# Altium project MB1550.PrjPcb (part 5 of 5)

## Sheet Camera.SchDoc: CAMERA
size A4; Date: Not used; ApprovedBy: Not used; CheckedBy: Not used; Author: Not used; CompanyName: STMicroelectronics; DrawnBy: Not used; Engineer: Not used; Organization: Not used; Address1: Not used; Address2: Not used; Address3: Not used; Address4: Not used; DocumentNumber: 17; Revision: Not used; SheetNumber: 17; SheetTotal: 24
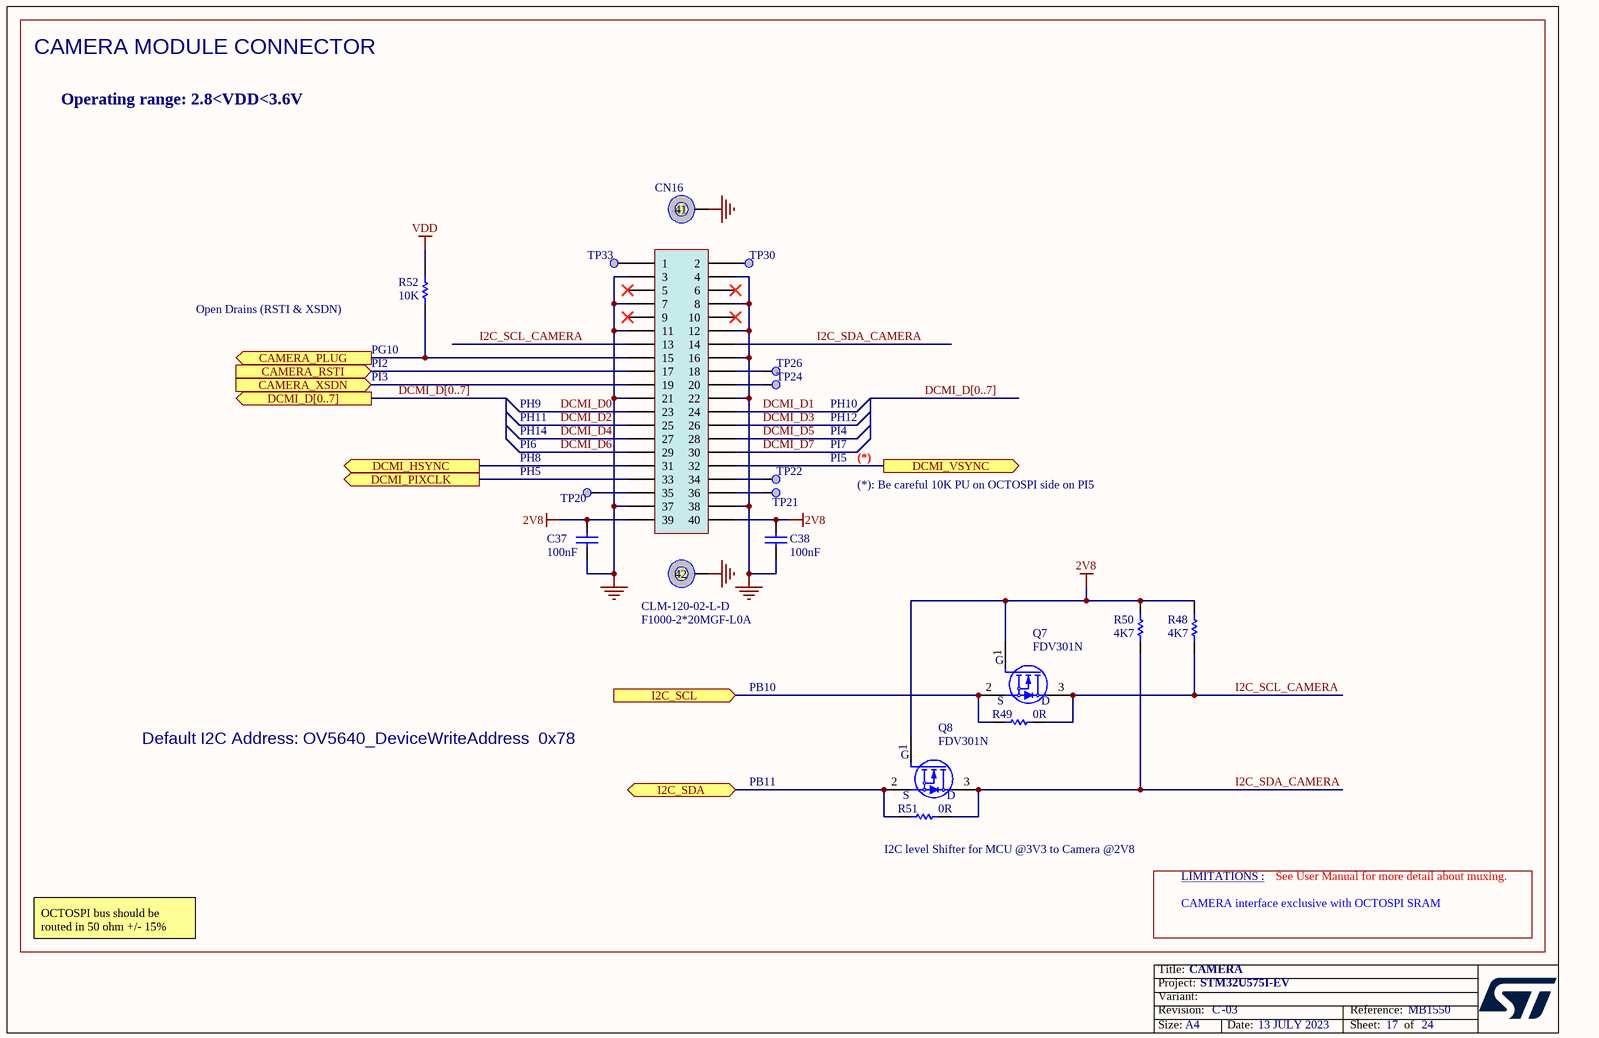
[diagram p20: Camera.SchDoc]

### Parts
C37  value 100nF  [C0402]
C38  value 100nF  [C0402]
CN16  value CLM-120-02-L-D  [CON_SAMTEC_CLM-120-02-L-D_Reverse-to-Camera]
Q7  value FDV301N  [MOS_SOT23]  (hidden comment: BSN20)
Q8  value FDV301N  [MOS_SOT23]  (hidden comment: BSN20)
R48  value 4K7  [R0402]
R49  value 0R  [R0603]  (hidden comment: Resistor)
R50  value 4K7  [R0402]
R51  value 0R  [R0603]  (hidden comment: Resistor)
R52  value 10K  [R0603]
TP20  Test Point  [TP_SMD_1MM]  (value not drawn)  (no BOM)
TP21  Test Point  [TP_SMD_1MM]  (value not drawn)  (no BOM)
TP22  Test Point  [TP_SMD_1MM]  (value not drawn)  (no BOM)
TP24  Test Point  [TP_SMD_1MM]  (value not drawn)  (no BOM)
TP26  Test Point  [TP_SMD_1MM]  (value not drawn)  (no BOM)
TP30  Test Point  [TP_SMD_1MM]  (value not drawn)  (no BOM)
TP33  Test Point  [TP_SMD_1MM]  (value not drawn)  (no BOM)

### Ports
CAMERA_PLUG (out), CAMERA_RSTI (in), CAMERA_XSDN (in), DCMI_D[0..7] (out), DCMI_HSYNC (out), DCMI_PIXCLK (out), DCMI_VSYNC (out), I2C_SCL (in), I2C_SDA (bidir)

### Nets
2V8: C37.2 C38.2 CN16.39 CN16.40 Q7.1(G) Q8.1(G) R48.2 R50.2
GND: C37.1 C38.1 CN16.3 CN16.4 CN16.7 CN16.8 CN16.11 CN16.12 CN16.16 CN16.21 CN16.22 CN16.37 CN16.38 CN16.41 CN16.42
VDD: R52.2
CAMERA_PLUG: CN16.15 R52.1 ; port CAMERA_PLUG
DCMI_D0: CN16.23
DCMI_D1: CN16.24
DCMI_D2: CN16.25
DCMI_D3: CN16.26
DCMI_D4: CN16.27
DCMI_D5: CN16.28
DCMI_D6: CN16.29
DCMI_D7: CN16.30
DCMI_PIXCLK: CN16.33 ; port DCMI_PIXCLK
I2C_SCL: Q7.2(S) R49.1 ; port I2C_SCL
I2C_SCL_CAMERA: CN16.13 Q7.3(D) R48.1 R49.2
I2C_SDA: Q8.2(S) R51.1 ; port I2C_SDA
I2C_SDA_CAMERA: CN16.14 Q8.3(D) R50.1 R51.2
PH8: CN16.31 ; port DCMI_HSYNC
PI2: CN16.17 ; port CAMERA_RSTI
PI3: CN16.19 ; port CAMERA_XSDN
PI5: CN16.32 ; port DCMI_VSYNC
NetCN16_1: CN16.1 TP33.1
NetCN16_2: CN16.2 TP30.1
NetCN16_18: CN16.18 TP26.1
NetCN16_20: CN16.20 TP24.1
NetCN16_34: CN16.34 TP22.1
NetCN16_35: CN16.35 TP20.1
NetCN16_36: CN16.36 TP21.1

Not connected (* = marked no-connect by the designer): CN16 5* 6* 9* 10*

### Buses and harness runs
bus DCMI_D[0..7]
bus DCMI_D[0..7] = port DCMI_D[0..7]

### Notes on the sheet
- CAMERA MODULE CONNECTOR
- Operating range: 2.8<VDD<3.6V
- Open Drains (RSTI & XSDN)
- (near R52) PG10
- PI2
- PI3
- PH9
- PH11
- PH14
- PI6
- PH10
- PH12
- PI4
- PI7
- PH8
- PH5
- PI5
- (*): Be careful 10K PU on OCTOSPI side on PI5
- (*)
- (near CN16) F1000-2*20MGF-L0A
- PB10
- Default I2C Address: OV5640_DeviceWriteAddress  0x78
- PB11
- (near R51) I2C level Shifter for MCU @3V3 to Camera @2V8
- LIMITATIONS :
- CAMERA interface exclusive with OCTOSPI SRAM
- See User Manual for more detail about muxing.
- OCTOSPI bus should be routed in 50 ohm +/- 15%

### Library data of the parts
C37 C38 = MCD-00006: Capacitor, MLCC, 100nF, 16V, X7R, 10%, 0402, T=0.5mm; Manufacturer_Part_Number: CC0402KRX7R7BB104; Manufacturer: YAGEO; Alternate_Manufacturer_Part_Number: GCM155R71C104KA55D; Alternate_Manufacturer: MURATA; Provided_By: SUBCO; ECCN_US: EAR99; ECCN_EU: NEC
CN16 = MCD-00138: Socket, 20x2, 1.0mm, VR, SMT, Height 2.26mm. Symbol & Footprint dedicated to MB1183 & MB1379 camera modules (not in line with Samtec datasheet); Part_Type: Connector; Provided_By: SUBCO; ECCN_US: EAR99; ECCN_EU: NEC
Q7 Q8 = MCD-02156: MOSFET, N-Channel , Vds: 25V, Id: 0,22A, Vgs(th): 1.06V, Vgs(max): +/-8V, Rdson:5ohm@Vgs=2.7V, Qg=0,49nC; Part_Type: Transistor; Manufacturer: ON SEMICONDUCTOR; ECCN_US: EAR99; ECCN_EU: NEC; Provided_By: SUBCO
R48 R50 = MCD-00065: Resistor,4K7,0402,1%,1/16W; Manufacturer_Part_Number: RC0402FR-074K7L; Manufacturer: YAGEO; Alternate_Manufacturer_Part_Number: RT0402FRE074K7L; Provided_By: SUBCO; ECCN_US: EAR99; ECCN_EU: NEC
R49 R51 = MCD-00056: Resistor,0R,0603,5%,1/10W; Manufacturer_Part_Number: RC0603JR-070RL; Manufacturer: YAGEO; Provided_By: SUBCO; ECCN_US: EAR99; ECCN_EU: NEC
R52 = MCD-00220: Resistor,10K,0603,1%,1/10W; Manufacturer_Part_Number: RC0603FR-0710KL; Manufacturer: YAGEO; Provided_By: Subcon; Initial_Board_Reference: MB1319
TP20-TP22 TP24 TP26 TP30 TP33 = MCD-00074: Test Point 1mm; Part_Type: Mechanical

## Sheet MFX_IO_expander.SchDoc: MFX IO EXPANDER
size A4; Date: Not used; ApprovedBy: Not used; CheckedBy: Not used; Author: Not used; CompanyName: STMicroelectronics; DrawnBy: Not used; Engineer: Not used; Organization: Not used; Address1: Not used; Address2: Not used; Address3: Not used; Address4: Not used; DocumentNumber: 6; Revision: Not used; SheetNumber: 6; SheetTotal: 24
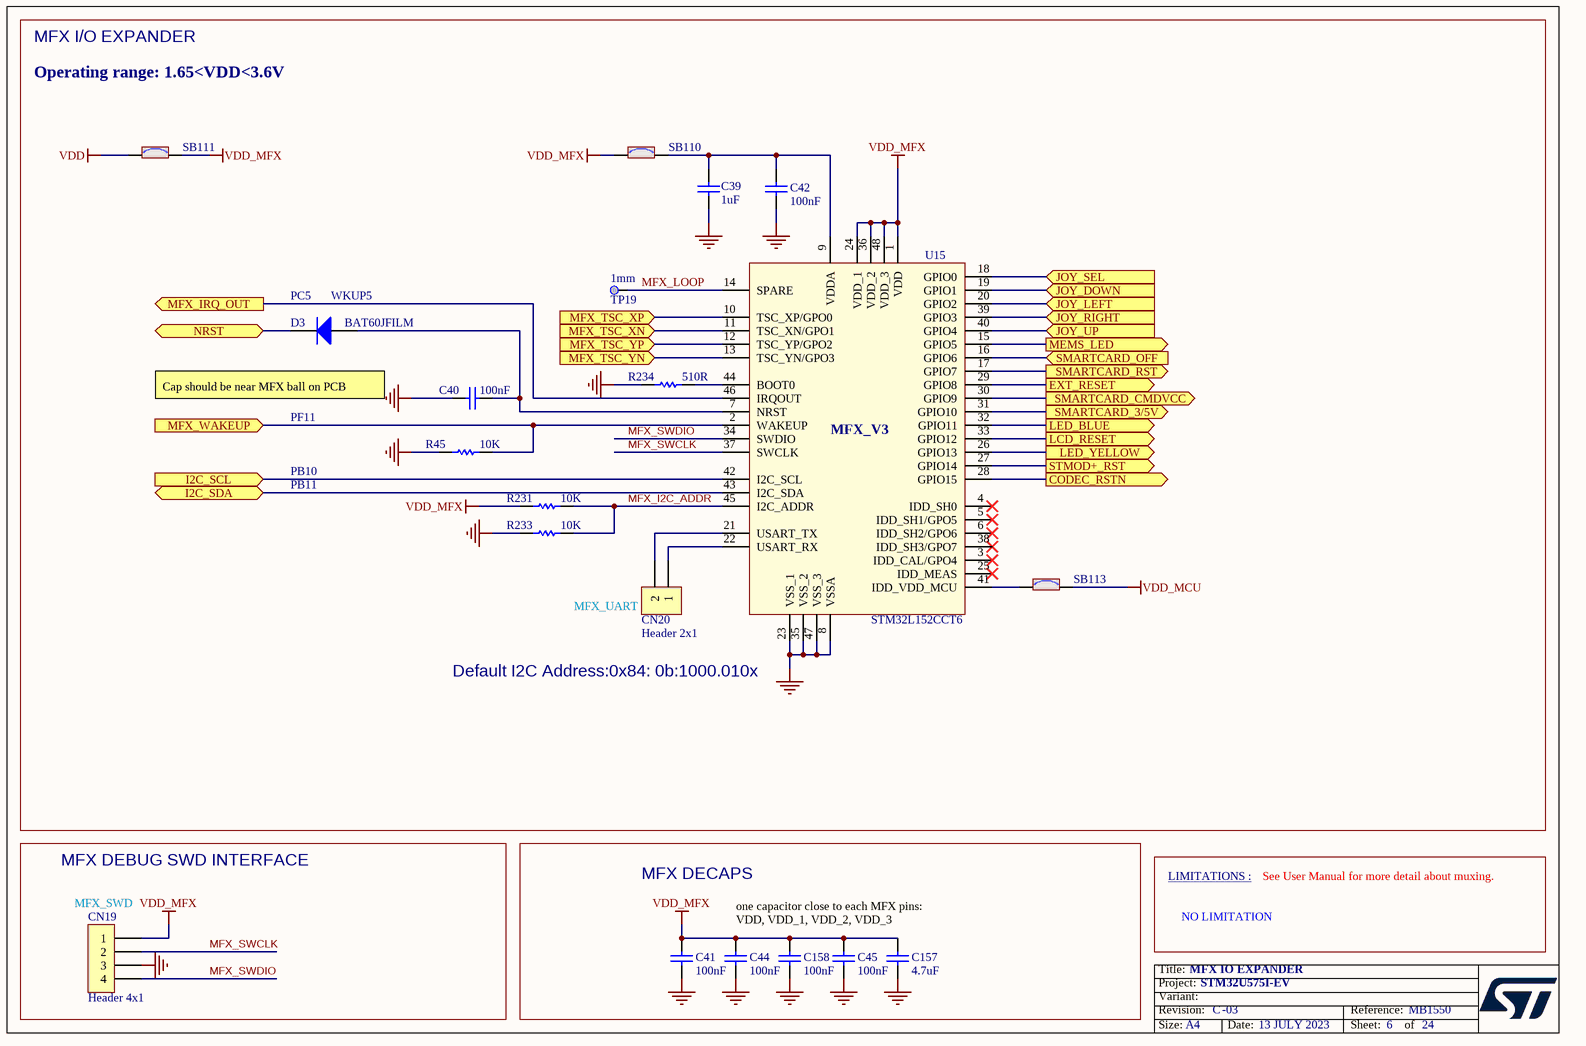
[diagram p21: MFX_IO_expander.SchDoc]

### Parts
C39  value 1uF  [C0603]
C40  value 100nF  [C0402]
C41  value 100nF  [C0402]
C42  value 100nF  [C0402]
C44  value 100nF  [C0402]
C45  value 100nF  [C0402]
C157  value 4.7uF  [C0603]
C158  value 100nF  [C0402]
CN19  value Header 4x1  [CON_SAMTEC_TSW-104-07-G-S]
CN20  value Header 2x1  [CON_SAMTEC_TSW-102-07-G-S]
D3  value BAT60JFILM  [DIO_SOD323]
R45  value 10K  [R0603]
R231  value 10K  [R0603]
R233  value 10K  [R0603]
R234  value 510R  [R0603]
SB110  (no value)  [SOLDER-BRIDGE_R0603-0R]
SB111  (no value)  [SOLDER-BRIDGE_R0603-0R]
SB113  (no value)  [SOLDER-BRIDGE_R0603-0R]
TP19  value 1mm  [TP_SMD_1MM]  (no BOM)
U15  value STM32L152CCT6  [ICC_LQFP48_7X7_P050]

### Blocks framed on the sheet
MFX DEBUG SWD INTERFACE: CN19
MFX DECAPS: C41 C44 C45 C157 C158

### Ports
CODEC_RSTN (out), EXT_RESET (out), I2C_SCL (in), I2C_SDA (bidir), JOY_DOWN (in), JOY_LEFT (in), JOY_RIGHT (in), JOY_SEL (in), JOY_UP (in), LCD_RESET (out), LED_BLUE (out), LED_YELLOW (out), MEMS_LED (out), MFX_IRQ_OUT (out), MFX_TSC_XN (in), MFX_TSC_XP (in), MFX_TSC_YN (in), MFX_TSC_YP (in), MFX_WAKEUP (in), NRST (bidir), SMARTCARD_3/5V (out), SMARTCARD_CMDVCC (out), SMARTCARD_OFF (in), SMARTCARD_RST (out), STMOD+_RST (out)

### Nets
GND: C39.1 C40.2 C41.1 C42.1 C44.1 C45.1 C157.1 C158.2 CN19.3 R45.1 R233.1 R234.1 U15.8(VSSA) U15.23(VSS_1) U15.35(VSS_2) U15.47(VSS_3)
VDD: SB111.1
VDD_MCU: SB113.2
VDD_MFX: C41.2 C44.2 C45.2 C157.2 C158.1 CN19.1 R231.1 SB110.1 SB111.2 U15.1(VDD) U15.24(VDD_1) U15.36(VDD_2) U15.48(VDD_3)
CODEC_RSTN: U15.28(GPIO15) ; port CODEC_RSTN
EXT_RESET: U15.29(GPIO8) ; port EXT_RESET
I2C_SCL: U15.42(I2C_SCL) ; port I2C_SCL
I2C_SDA: U15.43(I2C_SDA) ; port I2C_SDA
JOY_DOWN: U15.19(GPIO1) ; port JOY_DOWN
JOY_LEFT: U15.20(GPIO2) ; port JOY_LEFT
JOY_RIGHT: U15.39(GPIO3) ; port JOY_RIGHT
JOY_SEL: U15.18(GPIO0) ; port JOY_SEL
JOY_UP: U15.40(GPIO4) ; port JOY_UP
LCD_RESET: U15.33(GPIO12) ; port LCD_RESET
LED_BLUE: U15.32(GPIO11) ; port LED_BLUE
LED_YELLOW: U15.26(GPIO13) ; port LED_YELLOW
MEMS_LED: U15.15(GPIO5) ; port MEMS_LED
MFX_I2C_ADDR: R231.2 R233.2 U15.45(I2C_ADDR)
MFX_IRQ_OUT: U15.46(IRQOUT) ; port MFX_IRQ_OUT
MFX_LOOP: TP19.1 U15.14(SPARE)
MFX_SWCLK: CN19.2 U15.37(SWCLK)
MFX_SWDIO: CN19.4 U15.34(SWDIO)
MFX_TSC_XN: U15.11(TSC_XN/GPO1) ; port MFX_TSC_XN
MFX_TSC_XP: U15.10(TSC_XP/GPO0) ; port MFX_TSC_XP
MFX_TSC_YN: U15.13(TSC_YN/GPO3) ; port MFX_TSC_YN
MFX_TSC_YP: U15.12(TSC_YP/GPO2) ; port MFX_TSC_YP
MFX_WAKEUP: R45.2 U15.2(WAKEUP) ; port MFX_WAKEUP
NRST: D3.2(K) ; port NRST
SmartCard_3/5V: U15.31(GPIO10) ; port SMARTCARD_3/5V
SMARTCARD_CMDVCC: U15.30(GPIO9) ; port SMARTCARD_CMDVCC
SMARTCARD_OFF: U15.16(GPIO6) ; port SMARTCARD_OFF
SMARTCARD_RST: U15.17(GPIO7) ; port SMARTCARD_RST
STMOD+_RST: U15.27(GPIO14) ; port STMOD+_RST
NetC39_2: C39.2 C42.2 SB110.2 U15.9(VDDA)
NetC40_1: C40.1 D3.1(A) U15.7(NRST)
NetCN20_1: CN20.1 U15.22(USART_RX)
NetCN20_2: CN20.2 U15.21(USART_TX)
NetR234_2: R234.2 U15.44(BOOT0)
NetSB113_1: SB113.1 U15.41(IDD_VDD_MCU)

Not connected (* = marked no-connect by the designer): U15 3(IDD_CAL/GPO4)* 4(IDD_SH0)* 5(IDD_SH1/GPO5)* 6(IDD_SH2/GPO6)* 25(IDD_MEAS)* 38(IDD_SH3/GPO7)*

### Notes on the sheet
- MFX I/O EXPANDER
- Operating range: 1.65<VDD<3.6V
- (near D3) PC5
- (near D3) WKUP5
- (near D3) Cap should be near MFX ball on PCB
- PF11
- PB10
- PB11
- (near CN20) MFX_UART
- Default I2C Address:0x84: 0b:1000.010x
- (near CN19) MFX_SWD
- LIMITATIONS :
- NO LIMITATION
- See User Manual for more detail about muxing.
- one capacitor close to each MFX pins: VDD, VDD_1, VDD_2, VDD_3

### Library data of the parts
C39 = MCD-00010: Capacitor, MLCC, 1uF, 16V, X5R, 10%, 0603, T=0,8mm; Manufacturer_Part_Number: CC0603KRX5R7BB105; Manufacturer: YAGEO; Provided_By: Subcon; Initial_Board_Reference: MB1274
C40-C42 C44 C45 C158 = MCD-00006: as C37 on sheet Camera
C157 = MCD-00009: Capacitor, MLCC, 4.7uF, 16V, X5R, 10%, 0603, T=0.8mm; Manufacturer_Part_Number: CC0603KRX5R7BB475; Manufacturer: YAGEO; ECCN_US: EAR99; ECCN_EU: NEC; Provided_By: SUBCO
CN19 = MCD-00029: Header, 4x1, 2,54mm, VR, TH, Height 5.84mm/2.54mm; Manufacturer_Part_Number: TSW-104-07-x-S; Manufacturer: SAMTEC; Part_Type: Connector; Provided_By: Subcon; Initial_Board_Reference: MB1274
CN20 = MCD-00032: Header, 2x1, 2,54mm, VR, TH, Height 5.84mm/2.54mm; Part_Type: Connector; Manufacturer_Part_Number: TSW-102-07-x-S; Manufacturer: SAMTEC; Provided_By: Subcon; Initial_Board_Reference: MB1274
D3 = MCD-00034: BAT60JFILM; Manufacturer: STMICROELECTRONICS; Part_Type: Diode; ECCN_US: EAR99; ECCN_EU: NEC; Provided_By: Subcon; Initial_Board_Reference: MB1274
R45 R231 R233 = MCD-00220: as R52 on sheet Camera
R234 = MCD-00225: Resistor,510R,0603,1%,1/10W; Manufacturer_Part_Number: RC0603FR-07510RL; Manufacturer: YAGEO; Provided_By: Subcon; Initial_Board_Reference: MB1319
SB110 SB111 SB113 = MCD-00071: Solder Bridge ON; Part_Type: Mechanical; Provided_By: Subcon; Initial_Board_Reference: MB1274
TP19 = MCD-00074: Test Point 1mm; Part_Type: Mechanical; Initial_Board_Reference: MB1274
U15 = MCD-00135: Ultra-low-power 32-bit MCU ARM; Part_Type: IC; Manufacturer: STMICROELECTRONICS; BMS_Part_Number: 9175875; ECCN_US: 3A991A2; ECCN_EU: NEC; Provided_By: SUBCO with ST control

## Sheet STPMS2.SchDoc: STPMS2
size A4; Date: Not used; ApprovedBy: Not used; CheckedBy: Not used; Author: Not used; CompanyName: STMicroelectronics; DrawnBy: Not used; Engineer: Not used; Organization: Not used; Address1: Not used; Address2: Not used; Address3: Not used; Address4: Not used; DocumentNumber: 18; Revision: Not used; SheetNumber: 18; SheetTotal: 24
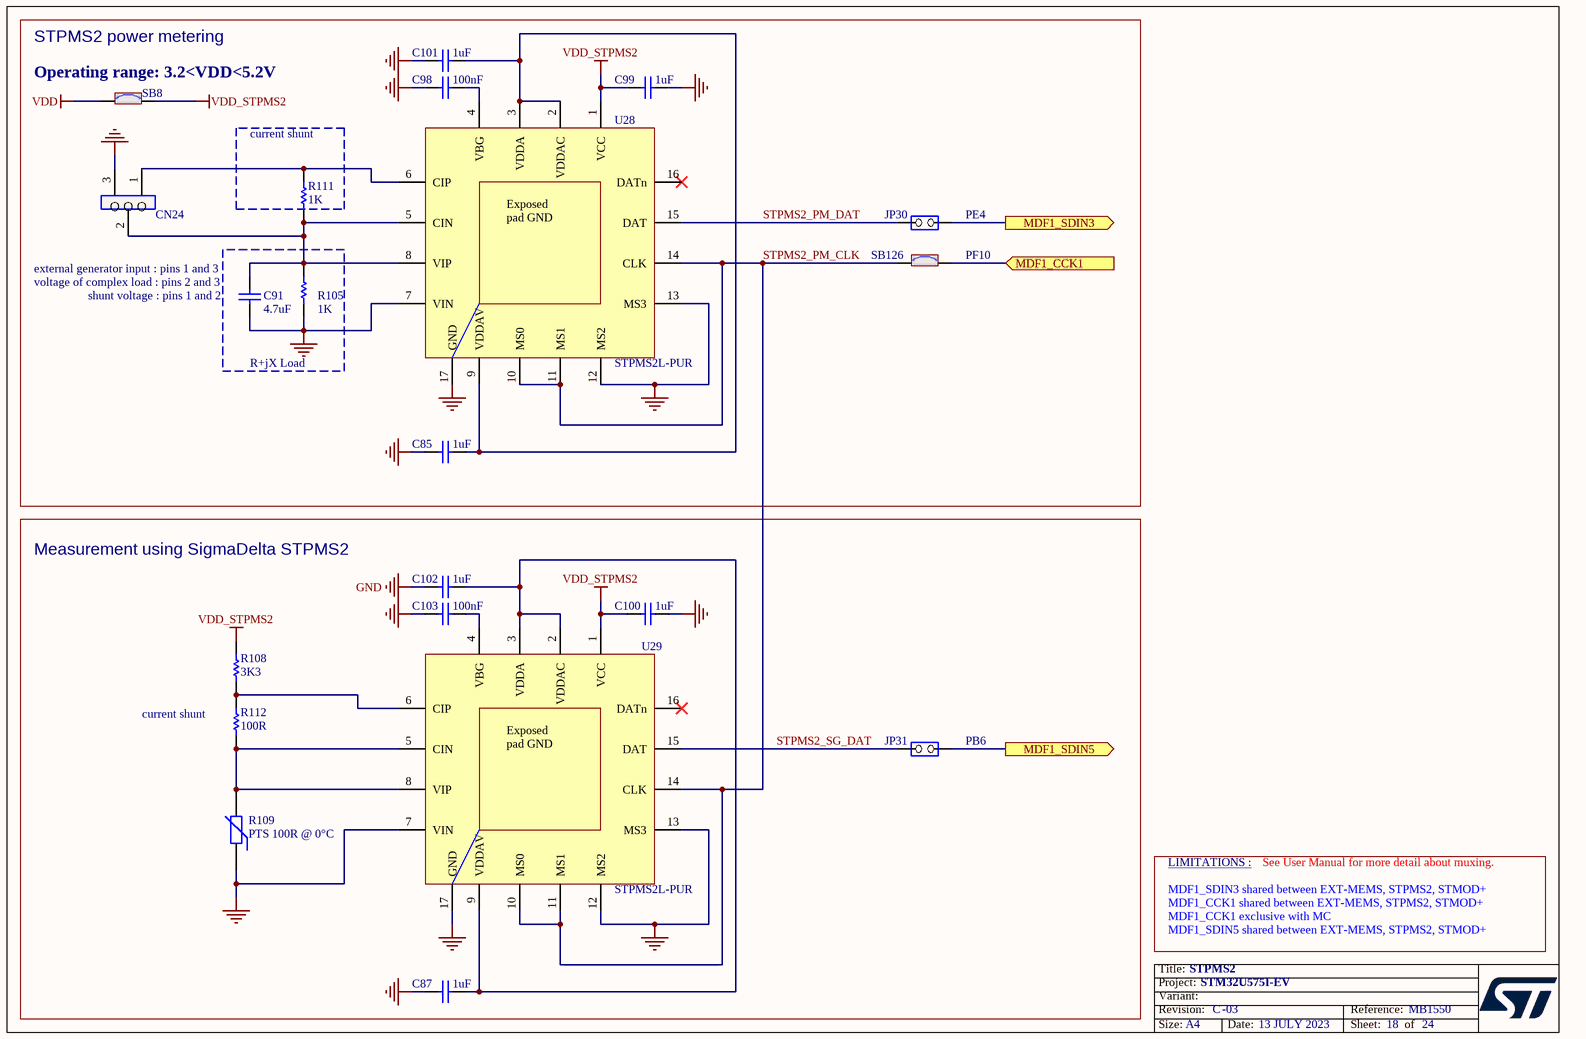
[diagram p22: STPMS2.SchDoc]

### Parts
C85  value 1uF  [C0603]
C87  value 1uF  [C0603]
C91  value 4.7uF  [C0603]
C98  value 100nF  [C0402]
C99  value 1uF  [C0603]
C100  value 1uF  [C0603]
C101  value 1uF  [C0603]
C102  value 1uF  [C0603]
C103  value 100nF  [C0402]
CN24  (no value)  [CON_SAMTEC_TSW-103-07-F-S]
JP30  Jumper_Header 2x1  [CON_SAMTEC_TSW-102-07-G-S]  (value not drawn)
JP31  Jumper_Header 2x1  [CON_SAMTEC_TSW-102-07-G-S]  (value not drawn)
R105  value 1K  [R0603]
R108  value 3K3  [R0603]
R109  value PTS 100R @ 0°C  [R0603_H0P45]  (hidden comment: PT100)
R111  value 1K  [R0603]
R112  value 100R  [R0603]
SB8  (no value)  [SOLDER-BRIDGE_R0603-0R]
SB126  (no value)  [SOLDER-BRIDGE_R0603-0R]
U28  value STPMS2L-PUR  [ICC_QFN16-EPAD_4X4_P065]
U29  value STPMS2L-PUR  [ICC_QFN16-EPAD_4X4_P065]

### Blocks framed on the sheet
STPMS2 power metering: C85 C98 C99 C101 CN24 JP30 SB8 SB126 U28
current shunt: R111
R+jX Load: C91 R105
Measurement using SigmaDelta STPMS2: C87 C100 C102 C103 JP31 R108 R109 R112 U29

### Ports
MDF1_CCK1 (in), MDF1_SDIN3 (out), MDF1_SDIN5 (out)

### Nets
GND: C85.1 C87.2 C91.1 C98.2 C99.1 C100.1 C101.2 C102.2 C103.1 CN24.3 R105.1 R109.1 U28.7(VIN) U28.12(MS2) U28.13(MS3) U28.17(GND) U29.7(VIN) U29.12(MS2) U29.13(MS3) U29.17(GND)
VDD: SB8.1
VDD_STPMS2: C99.2 C100.2 R108.2 SB8.2 U28.1(VCC) U29.1(VCC)
MDF1_CCK1: SB126.2 ; port MDF1_CCK1
MDF1_SDIN3: JP30.2(NO) ; port MDF1_SDIN3
MDF1_SDIN5: JP31.2(NO) ; port MDF1_SDIN5
STPMS2_PM_CLK: SB126.1 U28.10(MS0) U28.11(MS1) U28.14(CLK) U29.10(MS0) U29.11(MS1) U29.14(CLK)
STPMS2_PM_DAT: JP30.1(COMMON) U28.15(DAT)
STPMS2_SG_DAT: JP31.1(COMMON) U29.15(DAT)
NetC85_2: C85.2 C101.1 U28.2(VDDAC) U28.3(VDDA) U28.9(VDDAV)
NetC87_1: C87.1 C102.1 U29.2(VDDAC) U29.3(VDDA) U29.9(VDDAV)
NetC91_2: C91.2 CN24.2 R105.2 R111.1 U28.5(CIN) U28.8(VIP)
NetC98_1: C98.1 U28.4(VBG)
NetC103_2: C103.2 U29.4(VBG)
NetCN24_1: CN24.1 R111.2 U28.6(CIP)
NetR108_1: R108.1 R112.2 U29.6(CIP)
NetR109_2: R109.2 R112.1 U29.5(CIN) U29.8(VIP)

Not connected (* = marked no-connect by the designer): U28 16(DATn)*; U29 16(DATn)*

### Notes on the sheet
- (near SB8) Operating range: 3.2<VDD<5.2V
- PE4
- (near C91) external generator input : pins 1 and 3
- (near C91) voltage of complex load : pins 2 and 3
- (near C91) shunt voltage : pins 1 and 2
- (near SB126) PF10
- (near R112) current shunt
- (near JP31) PB6
- LIMITATIONS :
- MDF1_CCK1 shared between EXT-MEMS, STPMS2, STMOD+
- MDF1_CCK1 exclusive with MC
- MDF1_SDIN3 shared between EXT-MEMS, STPMS2, STMOD+
- See User Manual for more detail about muxing.
- MDF1_SDIN5 shared between EXT-MEMS, STPMS2, STMOD+

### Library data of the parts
C85 C87 C99-C102 = MCD-00010: as C39 on sheet MFX_IO_expander
C91 = MCD-00009: as C157 on sheet MFX_IO_expander
C98 C103 = MCD-00006: as C37 on sheet Camera
CN24 = MCD-00111: Header, 3x1, 2,54mm, VR, TH, Height 5.84mm/2.54mm; Manufacturer_Part_Number: TSW-103-07-F-S; Manufacturer: SAMTEC; Part_Type: Connector; Value: Header 3x1; Provided_By: Subcon; ECCN_US: EAR99; ECCN_EU: NEC; Initial_Board_Reference: MB1262
JP30 JP31 = MCD-00045: Header, 2x1, 2,54mm, VR, TH, Height 5.84mm/2.54mm; Part_Type: Connector; Manufacturer_Part_Number: TSW-102-07-x-S; Manufacturer: SAMTEC; Value: Shunt not fitted; Provided_By: Subcon; Initial_Board_Reference: MB1274; Remark: 3D KO: BZ: 40098
R105 R111 = MCD-00070: Resistor,1K,0603,1%,1/10W; Manufacturer_Part_Number: RC0603FR-071KL; Manufacturer: YAGEO; Provided_By: Subcon; Initial_Board_Reference: MB1274
R108 = MCD-00352: Resistor,3K3,0603,1%,1/10W; Manufacturer_Part_Number: RC0603FR-073K3L; Manufacturer: YAGEO; Provided_By: Subcon
R109 = MCD-00680: Resistor, SMD PTS 100ohm @ 0°C Flat Chip Temperature Sensor; Manufacturer_Part_Number: PTS060301B100RP100; Manufacturer: VISHAY; Provided_By: Subcon; Initial_Board_Reference: MB1331
R112 = MCD-00224: Resistor,100R,0603,1%,1/10W; Manufacturer_Part_Number: RC0603FR-07100RL; Manufacturer: YAGEO; Provided_By: Subcon; Initial_Board_Reference: MB1319
SB8 SB126 = MCD-00071: as SB110 on sheet MFX_IO_expander
U28 U29 = MCD-00681: Smart sensor II dual-channel 1-bit, 4 MHz, second-order sigmadelta modulator with embedded PGLNA; Part_Type: IC; Manufacturer: STMICROELECTRONICS; ECCN_US: EAR99; ECCN_EU: NEC; Provided_By: STM; Initial_Board_Reference: MB1331

## Sheet SENSOR_and_I2C-interface.SchDoc: SENSOR & I2C PERIPHERALS
size A4; Date: Not used; ApprovedBy: Not used; CheckedBy: Not used; Author: Not used; CompanyName: STMicroelectronics; DrawnBy: Not used; Engineer: Not used; Organization: Not used; Address1: Not used; Address2: Not used; Address3: Not used; Address4: Not used; DocumentNumber: 16; Revision: Not used; SheetNumber: 16; SheetTotal: 24
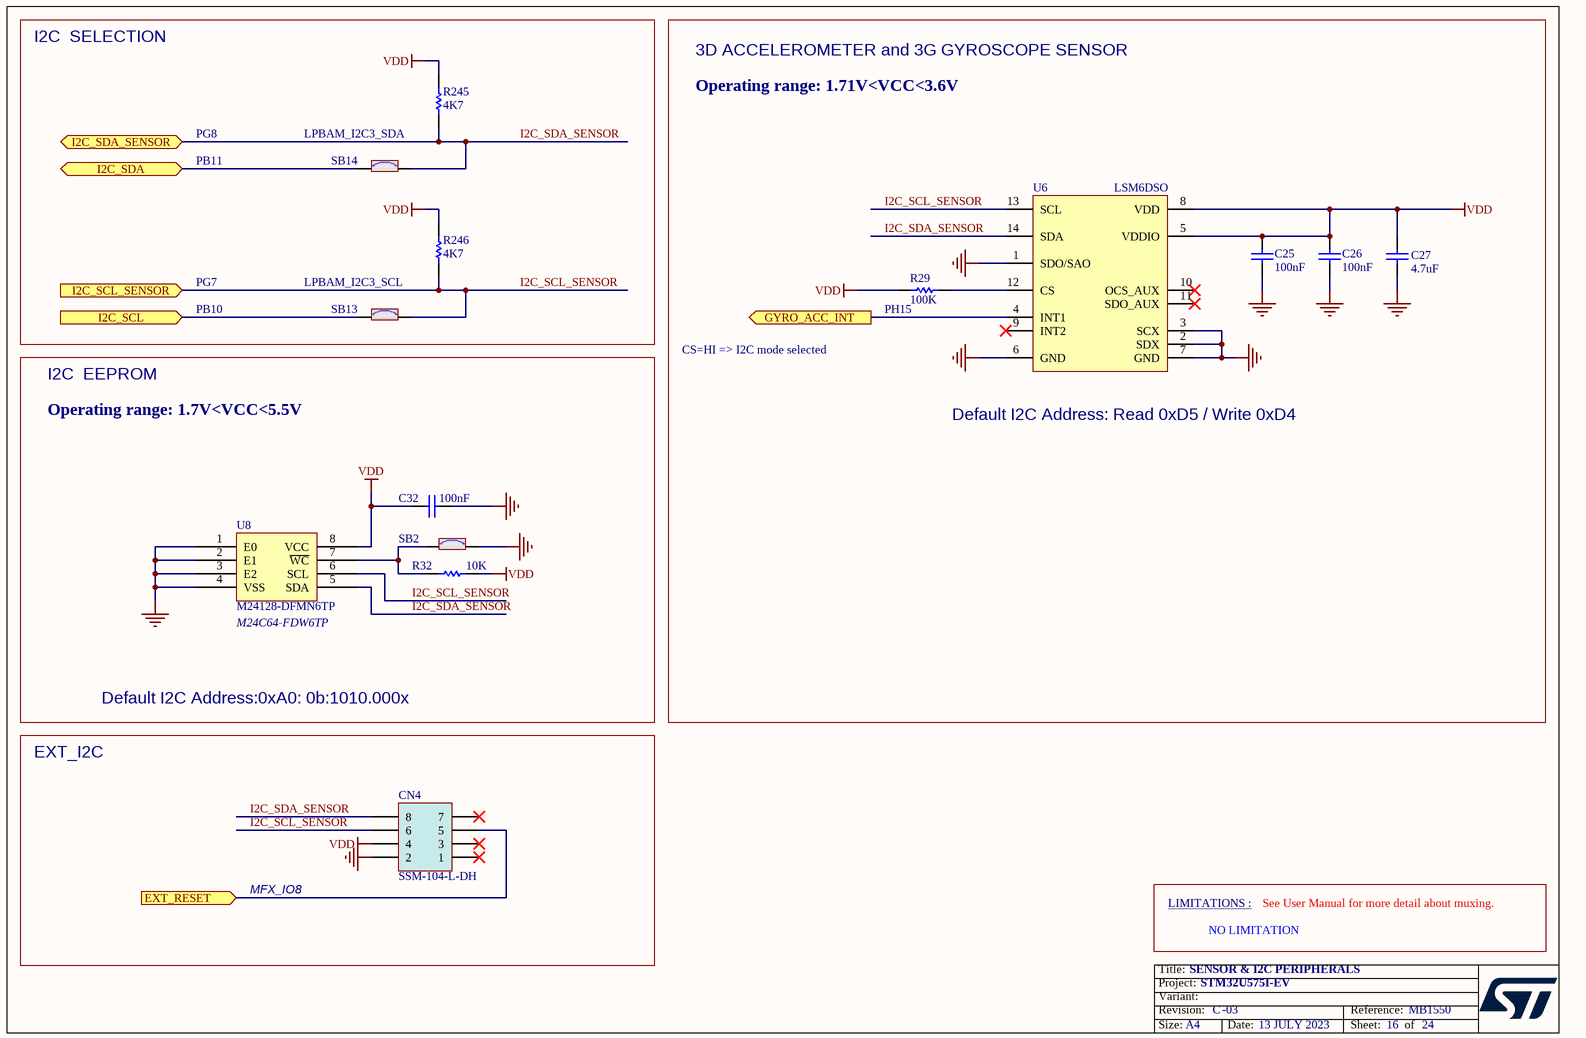
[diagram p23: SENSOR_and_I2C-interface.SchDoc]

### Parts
C25  value 100nF  [C0402]
C26  value 100nF  [C0402]
C27  value 4.7uF  [C0603]
C32  value 100nF  [C0402]
CN4  value SSM-104-L-DH  [CON_SAMTEC_SSM-104-L-DH]
R29  value 100K  [R0603]
R32  value 10K  [R0603]
R245  value 4K7  [R0603]  (hidden comment: Resistor)
R246  value 4K7  [R0603]  (hidden comment: Resistor)
SB2  (no value)  [SOLDER-BRIDGE_R0603-0R]
SB13  (no value)  [SOLDER-BRIDGE_R0603-0R]
SB14  (no value)  [SOLDER-BRIDGE_R0603-0R]
U6  LSM6DSO  [ICC_LGA14_3X2P5_P050]
U8  value M24128-DFMN6TP  [ICC_SO8_5X4_P127]

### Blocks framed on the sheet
I2C  SELECTION: R245 R246 SB13 SB14
EXT_I2C: CN4

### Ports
EXT_RESET (in), GYRO_ACC_INT (out), I2C_SCL (in), I2C_SCL_SENSOR (in), I2C_SDA (bidir), I2C_SDA_SENSOR (bidir)

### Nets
GND: C25.1 C26.1 C27.1 C32.1 CN4.2 SB2.2 U6.1(SDO/SAO) U6.2(SDX) U6.3(SCX) U6.6(GND) U6.7(GND) U8.1(E0) U8.2(E1) U8.3(E2) U8.4(VSS)
VDD: C25.2 C26.2 C27.2 C32.2 CN4.4 R29.2 R32.1 R245.2 R246.2 U6.5(VDDIO) U6.8(VDD) U8.8(VCC)
EXT_RESET: CN4.5 ; port EXT_RESET
GYRO_ACC_INT: U6.4(INT1) ; port GYRO_ACC_INT
I2C_SCL: SB13.1 ; port I2C_SCL
I2C_SCL_SENSOR: CN4.6 R246.1 SB13.2 U6.13(SCL) U8.6(SCL) ; port I2C_SCL_SENSOR
I2C_SDA: SB14.1 ; port I2C_SDA
I2C_SDA_SENSOR: CN4.8 R245.1 SB14.2 U6.14(SDA) U8.5(SDA) ; port I2C_SDA_SENSOR
NetR29_1: R29.1 U6.12(CS)
NetR32_2: R32.2 SB2.1 U8.7(~{WC})

Not connected (* = marked no-connect by the designer): CN4 1* 3* 7*; U6 9(INT2)* 10(OCS_AUX)* 11(SDO_AUX)*

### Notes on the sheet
- 3D ACCELEROMETER and 3G GYROSCOPE SENSOR
- Operating range: 1.71V<VCC<3.6V
- PB11
- PG8
- (near SB14) LPBAM_I2C3_SDA
- PB10
- PG7
- (near SB13) LPBAM_I2C3_SCL
- (near R29) PH15
- I2C  EEPROM
- CS=HI => I2C mode selected
- Operating range: 1.7V<VCC<5.5V
- (near U6) Default I2C Address: Read 0xD5 / Write 0xD4
- (near U8) M24C64-FDW6TP
- Default I2C Address:0xA0: 0b:1010.000x
- MFX_IO8
- LIMITATIONS :
- See User Manual for more detail about muxing.
- NO LIMITATION

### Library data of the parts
C25 C26 C32 = MCD-00006: as C37 on sheet Camera
C27 = MCD-00009: as C157 on sheet MFX_IO_expander
CN4 = MCD-00131: Socket, 4x2, 2.54mm, RA, SMT, Height 5.72mm; Manufacturer: SAMTEC; Part_Type: Connector; Provided_By: Subcon; ECCN_US: EAR99; ECCN_EU: NEC; Initial_Board_Reference: MB1262
R29 = MCD-00223: Resistor,100K,0603,1%,1/10W; Manufacturer_Part_Number: RC0603FR-07100KL; Manufacturer: YAGEO; Provided_By: Subcon; Initial_Board_Reference: MB1319
R32 = MCD-00220: as R52 on sheet Camera
R245 R246 = MCD-00219: Resistor,4K7,0603,1%,1/10W; Manufacturer_Part_Number: RC0603FR-074K7L; Manufacturer: YAGEO; Part_Preference: Recommended
SB2 SB13 SB14 = MCD-00071: as SB110 on sheet MFX_IO_expander
U6 = MCD-01499: iNEMO inertial module: always-on 3D accelerometer and 3D gyroscope; Part_Type: IC; Manufacturer: STMICROELECTRONICS; BMS_Part_Number: 9177993; ECCN_US: EAR99; ECCN_EU: NEC; Provided_By: SUBCO with ST control
U8 = MCD-00293: I2C memory; Part_Type: IC; Manufacturer: STMICROELECTRONICS; Provided_By: Subcon; Initial_Board_Reference: MB1329

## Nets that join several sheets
1V8: AUDIO (SB121.1), BOARD_PWR (SB7.2 TP34.1)
2V8: BOARD_PWR (SB104.2 TP16.1), Camera (8 pins)
3V3: BOARD_PWR (6 pins), Extension_Connector (CN9.50 CN14.34 CN15.34), FDCAN_RS232 (R78.1 SB56.1), MCU_PWR (JP5.1 JP17.3 JP23.1), MOTOR_CONTROL (CN2.28 R5.2 R6.1), PERIPHERAL (R130.2 R131.2 R132.2 R133.2), PMOD_STMOD+ (C1.2 R3.2 U1.2), USB_TYPEC (R1.2 R4.1 SB10.1 U42.2), LCD_TFT_320x240 (SB125.1 SB128.1), ST_LINK_V3E (R100.2)
5V: BOARD_PWR (14 pins), Extension_Connector (CN10.50), FDCAN_RS232 (SB5.1), MOTOR_CONTROL (CN2.25), PMOD_STMOD+ (CN7.6 CN7.15), SMARTCARD (SB118.1), LCD_TFT_320x240 (SB127.1), ST_LINK_V3E (R106.1)
5V_DC: BOARD_PWR (JP25.7), Extension_Connector (CN9.49), ST_LINK_V3E (D5.1)
5V_EXT: BOARD_PWR (7 pins), ST_LINK_V3E (D7.1)
5V_STLK: BOARD_PWR (JP25.1), ST_LINK_V3E (C61.1 U20.1)
5V_UCPD: BOARD_PWR (JP25.5), USB_TYPEC (JP6.1 JP7.1 JP8.1), ST_LINK_V3E (D6.1)
5V_USB_CHGR: BOARD_PWR (JP25.9), ST_LINK_V3E (8 pins)
GND: Top (H3.1 H4.1 H5.1 H6.1), AUDIO (34 pins), BOARD_PWR (42 pins), Extension_Connector (21 pins), FDCAN_RS232 (22 pins), JTAG_TRACE (26 pins), MCU_CLOCK_&_RESET (17 pins), MCU_IO (JP9.2 JP13.2), MCU_PWR (38 pins), MOTOR_CONTROL (26 pins), OCTOSPI (14 pins), PERIPHERAL (19 pins), PMOD_STMOD+ (8 pins), SDCARD (12 pins), SMARTCARD (17 pins), SRAM (6 pins), USB_TYPEC (29 pins), LCD_TFT_320x240 (13 pins), ST_LINK_V3E (107 pins), Camera (15 pins), MFX_IO_expander (16 pins), STPMS2 (20 pins), SENSOR_and_I2C-interface (15 pins)
VDD: AUDIO (9 pins), Extension_Connector (CN9.47 CN14.33 CN15.33), FDCAN_RS232 (6 pins), JTAG_TRACE (8 pins), MCU_CLOCK_&_RESET (5 pins), MCU_IO (R147.2 R149.2), MCU_PWR (JP19.1 JP23.2 JP24.1 TP12.1), OCTOSPI (SB28.1 SB109.1), PERIPHERAL (R34.1 R43.1 RV1.3), PMOD_STMOD+ (CN3.6 CN3.12), SDCARD (SB93.1), SMARTCARD (SB122.1), SRAM (SB106.1), LCD_TFT_320x240 (SB123.1), ST_LINK_V3E (7 pins), Camera (R52.2), MFX_IO_expander (SB111.1), STPMS2 (SB8.1), SENSOR_and_I2C-interface (12 pins)
VDD_ADJ: BOARD_PWR (SB3.2 TP29.1), MCU_PWR (JP23.3)
VDD_MCU: MCU_PWR (26 pins), MFX_IO_expander (SB113.2)
A0: MCU_IO (R205.2), SRAM (U12.A3)
A1: MCU_IO (R208.2), SRAM (U12.A4)
A2: MCU_IO (R214.2), SRAM (U12.A5)
A3: MCU_IO (R218.2), SRAM (U12.B3)
A4: MCU_IO (R223.2), SRAM (U12.B4)
A5: MCU_IO (R227.2), SRAM (U12.C3)
A6: MCU_IO (R225.2), SRAM (U12.C4)
A7: MCU_IO (R221.2), SRAM (U12.D4)
A8: MCU_IO (R219.2), SRAM (U12.H2)
A9: MCU_IO (R215.2), SRAM (U12.H3)
A10: MCU_IO (R209.2), SRAM (U12.H4)
A11: MCU_IO (R203.2), SRAM (U12.H5)
A12: MCU_IO (R217.2), SRAM (U12.G3)
A13: MCU_IO (R222.2), SRAM (U12.G4)
A14: MCU_IO (R226.2), SRAM (U12.F3)
A15: MCU_IO (R229.2), SRAM (U12.F4)
A16: MCU_IO (R196.1), SRAM (U12.E4)
A17: MCU_IO (R199.1), SRAM (U12.D3)
A18: MCU_IO (R204.1), SRAM (U12.H1)
A19: MCU_IO (R189.1), SRAM (U12.G2)
A20: MCU_IO (R191.2), SRAM (R38.1 U12.H6)
ADC_DAC: MCU_IO (SB16.2), PERIPHERAL (R144.2)
ADF1_CCK0: AUDIO (TP36.1 U37.16), MCU_IO (SB115.2)
ADF1_SDIN0: AUDIO (TP35.1 U37.5), MCU_IO (SB26.2)
BOOTLOADER_BOOT0: FDCAN_RS232 (U43.20), MCU_CLOCK_&_RESET (D1.1)
BOOTLOADER_RST: FDCAN_RS232 (R161.2 U43.16), MCU_CLOCK_&_RESET (D9.2)
CAMERA_PLUG: MCU_IO (SB103.2), Camera (CN16.15 R52.1)
CODEC_RSTN: AUDIO (R85.2 U25.25), MFX_IO_expander (U15.28)
COMP2_INP: MCU_IO (SB40.2), PERIPHERAL (JP22.1)
COMP2_OUT: MCU_IO (SB39.2), PERIPHERAL (TP9.1)
D0: MCU_IO (R207.1), SRAM (U12.B6), LCD_TFT_320x240 (CN23.6)
D1: MCU_IO (R213.1), SRAM (U12.C5), LCD_TFT_320x240 (CN23.7)
D2: MCU_IO (R228.1), SRAM (U12.C6), LCD_TFT_320x240 (CN23.8)
D3: MCU_IO (R224.1), SRAM (U12.D5), LCD_TFT_320x240 (CN23.9)
D4: MCU_IO (R200.1), SRAM (U12.E5), LCD_TFT_320x240 (CN23.10)
D5: MCU_IO (R197.1), SRAM (U12.F5), LCD_TFT_320x240 (CN23.11)
D6: MCU_IO (R193.1), SRAM (U12.F6), LCD_TFT_320x240 (CN23.12)
D7: MCU_IO (R188.1), SRAM (U12.G6), LCD_TFT_320x240 (CN23.13)
D8: MCU_IO (R185.1), SRAM (U12.B1), LCD_TFT_320x240 (CN23.14)
D9: MCU_IO (R182.1), SRAM (U12.C1), LCD_TFT_320x240 (CN23.15)
D10: MCU_IO (R180.1), SRAM (U12.C2), LCD_TFT_320x240 (CN23.16)
D11: MCU_IO (R175.1), SRAM (U12.D2), LCD_TFT_320x240 (CN23.17)
D12: MCU_IO (R183.1), SRAM (U12.E2), LCD_TFT_320x240 (CN23.18)
D13: MCU_IO (R186.1), SRAM (U12.F2), LCD_TFT_320x240 (CN23.19)
D14: MCU_IO (R190.1), SRAM (U12.F1), LCD_TFT_320x240 (CN23.20)
D15: MCU_IO (R192.1), SRAM (U12.G1), LCD_TFT_320x240 (CN23.21)
DCMI_D0: Extension_Connector (CN10.17), MCU_IO (SB95.1 U5.E9), Camera (CN16.23)
DCMI_D1: Extension_Connector (CN10.18), MCU_IO (SB97.1 U5.C13), Camera (CN16.24)
DCMI_D2: Extension_Connector (CN10.20), MCU_IO (SB99.1 U5.D9), Camera (CN16.25)
DCMI_D3: Extension_Connector (CN10.21), MCU_IO (SB100.1 U5.B13), Camera (CN16.26)
DCMI_D4: Extension_Connector (CN10.22), MCU_IO (U5.C11), Camera (CN16.27)
DCMI_D5: Extension_Connector (CN10.8), MCU_IO (U5.B10), Camera (CN16.28)
DCMI_D6: Extension_Connector (CN10.12), MCU_IO (U5.A2), Camera (CN16.29)
DCMI_D7: Extension_Connector (CN10.11), MCU_IO (U5.C3), Camera (CN16.30)
DCMI_PIXCLK: MCU_IO (R145.1), Camera (CN16.33)
EXT_RESET: MFX_IO_expander (U15.29), SENSOR_and_I2C-interface (CN4.5)
FMC_A22_LCD_RS: MCU_IO (R198.1), LCD_TFT_320x240 (CN23.2)
FMC_NBL0: MCU_IO (R176.1), SRAM (U12.A1)
FMC_NBL1: MCU_IO (R181.1), SRAM (U12.B2)
FMC_NE1: MCU_IO (R202.1), SRAM (R37.1 U12.B5)
FMC_NE4_LCD_CSn: MCU_IO (R187.2), LCD_TFT_320x240 (CN23.1)
FMC_NOE: MCU_IO (R216.1), SRAM (U12.A2), LCD_TFT_320x240 (CN23.4)
FMC_NWE: MCU_IO (R210.1), SRAM (U12.G5), LCD_TFT_320x240 (CN23.3)
GYRO_ACC_INT: MCU_IO (SB27.1), SENSOR_and_I2C-interface (U6.4)
I2C_SCL: AUDIO (U25.3), MCU_IO (R147.1 SB46.1 TP8.1), PMOD_STMOD+ (CN7.7), USB_TYPEC (U42.18), LCD_TFT_320x240 (SB138.2 U35.9), Camera (Q7.2 R49.1), MFX_IO_expander (U15.42), SENSOR_and_I2C-interface (SB13.1)
I2C_SCL_SENSOR: MCU_IO (JP10.1), SENSOR_and_I2C-interface (5 pins)
I2C_SDA: AUDIO (U25.2), MCU_IO (R149.1 SB49.1 TP7.1), PMOD_STMOD+ (CN7.10), USB_TYPEC (U42.17), LCD_TFT_320x240 (SB141.2 U35.8), Camera (Q8.2 R51.1), MFX_IO_expander (U15.43), SENSOR_and_I2C-interface (SB14.1)
I2C_SDA_SENSOR: MCU_IO (JP11.1), SENSOR_and_I2C-interface (5 pins)
IBUS_SENSE: MCU_IO (SB72.2), USB_TYPEC (U42.4)
JOY_DOWN: PERIPHERAL (B1.3 U38.4), MFX_IO_expander (U15.19)
JOY_LEFT: PERIPHERAL (B1.1 U38.6), MFX_IO_expander (U15.20)
JOY_RIGHT: PERIPHERAL (B1.6 U38.3), MFX_IO_expander (U15.39)
JOY_SEL: PERIPHERAL (B1.2 U38.5), MFX_IO_expander (U15.18)
JOY_UP: PERIPHERAL (B1.4 U38.1), MFX_IO_expander (U15.40)
JTCK_SWCLK: Extension_Connector (CN10.4), JTAG_TRACE (R58.2), MCU_IO (U5.C10), ST_LINK_V3E (CN13.4 CN18.6 R71.1 U17.4)
JTDI: JTAG_TRACE (R46.2), MCU_IO (SB15.2), ST_LINK_V3E (CN13.8 CN18.10 U17.1)
JTDO_SWO: JTAG_TRACE (R62.2), MCU_IO (SB114.2), ST_LINK_V3E (CN13.6 CN18.8 R70.1 U17.3)
JTMS_SWDIO: Extension_Connector (CN10.2), JTAG_TRACE (R54.2), MCU_IO (U5.F12), ST_LINK_V3E (CN13.2 CN18.4 R72.1 U17.5)
JTRSTN: JTAG_TRACE (R40.2), MCU_IO (SB32.2), ST_LINK_V3E (CN13.9)
LCD_CTP_INT: MCU_IO (SB35.2), LCD_TFT_320x240 (R119.1 SB137.2 U35.7)
LCD_RESET: LCD_TFT_320x240 (CN23.5), MFX_IO_expander (U15.33)
LCD_TE: MCU_IO (SB117.2), LCD_TFT_320x240 (SB143.2)
LED_BLUE: PERIPHERAL (R238.1), MFX_IO_expander (U15.32)
LED_YELLOW: PERIPHERAL (R237.1), MFX_IO_expander (U15.26)
MC_BUS_VOLTAGE: MCU_IO (SB17.2), MOTOR_CONTROL (C15.2 CN2.14 R7.2)
MC_CURRENT_A: MCU_IO (SB63.2), MOTOR_CONTROL (C11.1 CN2.15)
MC_CURRENT_B: MCU_IO (SB66.2), MOTOR_CONTROL (C4.1 CN2.17)
MC_CURRENT_C: MCU_IO (SB73.2), MOTOR_CONTROL (C3.2 CN2.19)
MC_DISSIPATIVE_BRAKE: MCU_IO (SB45.2), MOTOR_CONTROL (CN2.23)
MC_EMERGENCY_STOP: MCU_IO (SB43.2), MOTOR_CONTROL (C10.1 CN2.1 R6.2)
MC_ENCODER_A: MCU_IO (SB65.2), MOTOR_CONTROL (C8.1 CN2.31 SB1.1)
MC_ENCODER_B: MCU_IO (SB67.2), MOTOR_CONTROL (C6.1 CN2.33)
MC_ENCODER_INDEX: MCU_IO (SB48.2), MOTOR_CONTROL (C7.2 CN2.34)
MC_ICL_SHUTOUT: MCU_IO (SB107.2), MOTOR_CONTROL (CN2.21)
MC_PFC_IND_CURR: MCU_IO (SB69.2), MOTOR_CONTROL (C14.2 CN2.24)
MC_PFC_PWM: MCU_IO (SB58.2), MOTOR_CONTROL (C9.1 CN2.29)
MC_PFC_SHUTDOWN: MCU_IO (SB44.2), MOTOR_CONTROL (C2.2 CN2.30 R5.1)
MC_PFC_SYNC: MCU_IO (SB59.2), MOTOR_CONTROL (C12.2 CN2.27)
MC_PFC_VAC: MCU_IO (SB57.2), MOTOR_CONTROL (C5.2 CN2.32)
MC_PWM_1H: MCU_IO (SB29.2), MOTOR_CONTROL (CN2.3)
MC_PWM_1L: MCU_IO (SB61.2), MOTOR_CONTROL (CN2.5)
MC_PWM_2H: MCU_IO (SB30.2), MOTOR_CONTROL (CN2.7)
MC_PWM_2L: MCU_IO (SB50.2), MOTOR_CONTROL (CN2.9)
MC_PWM_3H: MCU_IO (SB80.2), MOTOR_CONTROL (CN2.11)
MC_PWM_3L: MCU_IO (SB54.2), MOTOR_CONTROL (CN2.13)
MC_TEMP: MCU_IO (SB51.2), MOTOR_CONTROL (C13.2 CN2.26)
MDF1_CCK0: AUDIO (TP37.1 U37.8), MCU_IO (SB119.2)
MDF1_CCK1: AUDIO (CN29.3), MCU_IO (SB55.2), PMOD_STMOD+ (CN7.18 R146.1), STPMS2 (SB126.2)
MDF1_SDIN0: AUDIO (TP38.1 U37.13), MCU_IO (R220.1)
MDF1_SDIN3: AUDIO (CN29.5), MCU_IO (SB105.2), PMOD_STMOD+ (CN7.17), STPMS2 (JP30.2)
MDF1_SDIN5: AUDIO (CN29.7), MCU_IO (SB41.2), PMOD_STMOD+ (CN7.19), STPMS2 (JP31.2)
MEMS_LED: AUDIO (CN29.12), MFX_IO_expander (U15.15)
MFX_IRQ_OUT: MCU_IO (SB70.2), MFX_IO_expander (U15.46)
MFX_TSC_XN: LCD_TFT_320x240 (SB142.2), MFX_IO_expander (U15.11)
MFX_TSC_XP: LCD_TFT_320x240 (SB136.2), MFX_IO_expander (U15.10)
MFX_TSC_YN: LCD_TFT_320x240 (SB140.2), MFX_IO_expander (U15.13)
MFX_TSC_YP: LCD_TFT_320x240 (SB139.2), MFX_IO_expander (U15.12)
MFX_WAKEUP: MCU_IO (SB60.2), MFX_IO_expander (R45.2 U15.2)
NRST: Extension_Connector (R156.1), JTAG_TRACE (R53.2), MCU_CLOCK_&_RESET (5 pins), MCU_IO (U5.H3), OCTOSPI (R211.1 SB64.1), LCD_TFT_320x240 (R120.1), ST_LINK_V3E (CN13.10 CN18.12 R69.1), MFX_IO_expander (D3.2)
OCTOSPI_1_CLK_N: MCU_IO (SB47.2), OCTOSPI (CN11.15)
OCTOSPI_1_CLK_P: MCU_IO (R150.2), OCTOSPI (CN11.17)
OCTOSPI_1_DQS: MCU_IO (R148.2), OCTOSPI (CN11.11)
OCTOSPI_1_IO0: MCU_IO (R155.2), OCTOSPI (CN11.3)
OCTOSPI_1_IO1: MCU_IO (R152.2), OCTOSPI (CN11.5)
OCTOSPI_1_IO2: MCU_IO (R159.2), OCTOSPI (CN11.7)
OCTOSPI_1_IO3: MCU_IO (R158.2), OCTOSPI (CN11.9)
OCTOSPI_1_IO4: MCU_IO (R163.2), OCTOSPI (CN11.8)
OCTOSPI_1_IO5: MCU_IO (R162.2), OCTOSPI (CN11.10)
OCTOSPI_1_IO6: MCU_IO (R164.2), OCTOSPI (CN11.12)
OCTOSPI_1_IO7: MCU_IO (R160.2), OCTOSPI (CN11.14)
OCTOSPI_1_NCS: MCU_IO (R151.2), OCTOSPI (CN11.6 R24.1)
OCTOSPI_2_CLK: MCU_IO (R179.1), OCTOSPI (U47.B2)
OCTOSPI_2_DQS: MCU_IO (R178.1), OCTOSPI (U47.C3)
OCTOSPI_2_IO0: MCU_IO (SB98.2), OCTOSPI (U47.D3)
OCTOSPI_2_IO1: MCU_IO (SB101.2), OCTOSPI (U47.D2)
OCTOSPI_2_IO2: MCU_IO (R177.1), OCTOSPI (U47.C4)
OCTOSPI_2_IO3: MCU_IO (SB96.2), OCTOSPI (U47.D4)
OCTOSPI_2_IO4: MCU_IO (SB95.2), OCTOSPI (U47.D5)
OCTOSPI_2_IO5: MCU_IO (SB97.2), OCTOSPI (U47.E3)
OCTOSPI_2_IO6: MCU_IO (SB99.2), OCTOSPI (U47.E2)
OCTOSPI_2_IO7: MCU_IO (SB100.2), OCTOSPI (U47.E1)
OCTOSPI_2_NCS: MCU_IO (SB112.2), OCTOSPI (JP20.2 R212.2)
OPAMP1_INM: MCU_IO (TP15.1 U5.M1), PERIPHERAL (R43.2 R44.2 RV2.1)
OPAMP1_INP: MCU_IO (SB68.2), PERIPHERAL (R39.2)
OPAMP1_VOUT: MCU_IO (SB53.2), PERIPHERAL (RV2.2 RV2.3 TP18.1)
PA0: Extension_Connector (CN9.42), MCU_IO (5 pins)
PA1: Extension_Connector (CN9.43), MCU_IO (SB67.1 SB71.1 SB78.1 U5.L3)
PA2: Extension_Connector (CN10.26), MCU_IO (R151.1 SB48.1 U5.M2)
PA3: Extension_Connector (CN10.25), MCU_IO (R150.1 SB51.1 SB53.1 U5.N2)
PA4: Extension_Connector (CN9.44), MCU_IO (SB16.1 SB17.1 SB18.1 U5.N1)
PA5: Extension_Connector (CN9.45), MCU_IO (SB75.1 SB82.1 U5.K4)
PA6: Extension_Connector (CN10.34), MCU_IO (R158.1 SB57.1 U5.N4)
PA7: Extension_Connector (CN10.36), MCU_IO (R159.1 SB61.1 U5.J5)
PA8: Extension_Connector (CN9.46), MCU_IO (U5.G7), LCD_TFT_320x240 (R91.1)
PA9: Extension_Connector (CN10.1), MCU_IO (U5.G11), ST_LINK_V3E (CN18.14 R66.1 U14.3)
PA10: Extension_Connector (CN10.3), MCU_IO (U5.F11), ST_LINK_V3E (CN18.13 R68.2 U14.1)
PA11: Extension_Connector (CN9.1), MCU_IO (R139.2)
PA12: Extension_Connector (CN9.3), MCU_IO (R140.2)
PA15: Extension_Connector (CN9.2), MCU_IO (SB15.1 SB19.1 U5.A10)
PB0: Extension_Connector (CN10.28), MCU_IO (R152.1 SB50.1 U5.K5)
PB1: Extension_Connector (CN10.32), MCU_IO (R155.1 SB54.1 U5.N5)
PB2: Extension_Connector (CN10.24), MCU_IO (R148.1 SB45.1 U5.L5)
PB3: Extension_Connector (CN9.15), MCU_IO (SB114.1 SB115.1 U5.D6)
PB4: Extension_Connector (CN9.16), MCU_IO (5 pins)
PB5: Extension_Connector (CN9.17), MCU_IO (JP13.1 SB36.1 SB39.1 U5.C6)
PB6: Extension_Connector (CN9.18), MCU_IO (SB41.1 SB43.1 U5.B5)
PB7: Extension_Connector (CN14.1), MCU_IO (U5.F5), PERIPHERAL (R240.1)
PB8: Extension_Connector (CN9.20), FDCAN_RS232 (JP29.1), MCU_IO (SB119.1 U5.E5), USB_TYPEC (JP14.1)
PB9: Extension_Connector (CN9.21), FDCAN_RS232 (JP27.1), MCU_IO (U5.D5), USB_TYPEC (JP15.1)
PB10: Extension_Connector (CN9.22), MCU_IO (SB46.2 U5.K9)
PB11: Extension_Connector (CN9.23), MCU_IO (SB49.2 U5.L9)
PB12: Extension_Connector (CN10.23), MCU_IO (SB42.1 SB44.1 SB47.1 U5.L10)
PB13: Extension_Connector (CN9.24), MCU_IO (SB34.2)
PB14: Extension_Connector (CN9.25), MCU_IO (SB23.2)
PB15: Extension_Connector (CN9.27), MCU_IO (SB52.2 U5.L11)
PC0: Extension_Connector (CN10.37), MCU_IO (R160.1 SB63.1 U5.J2)
PC1: Extension_Connector (CN10.38), MCU_IO (R163.1 SB66.1 U5.J3)
PC2: Extension_Connector (CN10.39), MCU_IO (R162.1 SB73.1 U5.J4)
PC3: Extension_Connector (CN10.40), MCU_IO (R164.1 SB69.1 U5.K1)
PC4: Extension_Connector (CN9.37), MCU_IO (SB116.1 SB117.1 U5.L4)
PC5: Extension_Connector (CN9.40), MCU_IO (SB70.1 U5.M4)
PC6: Extension_Connector (CN9.4), MCU_IO (SB24.2)
PC7: Extension_Connector (CN9.6), MCU_IO (SB25.2)
PC8: Extension_Connector (CN10.43), MCU_IO (SB80.1 SB84.1 U5.G10)
PC9: Extension_Connector (CN10.44), MCU_IO (SB77.1 SB83.1 U5.G9)
PC10: Extension_Connector (CN10.45), MCU_IO (SB81.1 SB85.1 U5.C9)
PC11: Extension_Connector (CN10.46), MCU_IO (R168.1 U5.A9)
PC12: Extension_Connector (CN10.47), MCU_IO (SB91.1 SB92.1 SB94.1 U5.E8)
PC13: Extension_Connector (CN9.26), MCU_CLOCK_&_RESET (C146.2 JP35.3 R125.1), MCU_IO (U5.E3)
PC14: Extension_Connector (CN9.30), MCU_CLOCK_&_RESET (SB87.1)
PC14-OSC32_IN: MCU_CLOCK_&_RESET (R27.1 SB87.2), MCU_IO (U5.D1)
PC15: Extension_Connector (CN9.32), MCU_CLOCK_&_RESET (SB86.1)
PC15-OSC32_OUT: MCU_CLOCK_&_RESET (R28.1 SB86.2), MCU_IO (U5.E1)
PD0: Extension_Connector (CN14.27), MCU_IO (R228.2 U5.B9)
PD1: Extension_Connector (CN14.25), MCU_IO (R224.2 U5.F6)
PD2: Extension_Connector (CN10.48), MCU_IO (R171.2 U5.F7)
PD3: Extension_Connector (CN14.23), MCU_IO (R220.2 U5.D8)
PD4: Extension_Connector (CN14.21), MCU_IO (R216.2 U5.C8)
PD5: Extension_Connector (CN14.19), MCU_IO (R210.2 U5.E7)
PD6: Extension_Connector (CN14.17), MCU_IO (R206.2 U5.B7)
PD7: Extension_Connector (CN14.15), MCU_IO (R202.2 U5.D7)
PD8: Extension_Connector (CN15.6), MCU_IO (R186.2 U5.L12)
PD9: Extension_Connector (CN15.8), MCU_IO (R190.2 U5.L13)
PD10: Extension_Connector (CN15.12), MCU_IO (R192.2 U5.K11)
PD11: Extension_Connector (CN15.14), MCU_IO (R196.2 U5.M13)
PD12: Extension_Connector (CN15.16), MCU_IO (R199.2 U5.K10)
PD13: Extension_Connector (CN15.18), MCU_IO (R204.2 U5.K12)
PD14: Extension_Connector (CN15.20), MCU_IO (R207.2 U5.J10)
PD15: Extension_Connector (CN15.22), MCU_IO (R213.2 U5.J11)
PE0: Extension_Connector (CN14.2), MCU_IO (R176.2 U5.D4)
PE1: Extension_Connector (CN14.4), MCU_IO (R181.2 U5.C4)
PE2: Extension_Connector (CN14.6), MCU_IO (R184.2 U5.A1)
PE3: Extension_Connector (CN14.8), MCU_IO (R189.2 U5.D3)
PE4: Extension_Connector (CN14.12), MCU_IO (R191.1 SB105.1 U5.C2)
PE5: Extension_Connector (CN14.14), MCU_IO (R194.2 U5.D2)
PE6: Extension_Connector (CN14.16), MCU_IO (R198.2 U5.E4)
PE7: Extension_Connector (CN15.15), MCU_IO (R200.2 U5.L7)
PE8: Extension_Connector (CN15.13), MCU_IO (R197.2 U5.K7)
PE9: Extension_Connector (CN15.11), MCU_IO (R193.2 U5.J7)
PE10: Extension_Connector (CN15.7), MCU_IO (R188.2 U5.H8)
PE11: Extension_Connector (CN15.5), MCU_IO (R185.2 U5.M8)
PE12: Extension_Connector (CN15.3), MCU_IO (R182.2 U5.N8)
PE13: Extension_Connector (CN15.1), MCU_IO (R180.2 U5.L8)
PE14: Extension_Connector (CN15.2), MCU_IO (R175.2 U5.K8)
PE15: Extension_Connector (CN15.4), MCU_IO (R183.2 U5.M9)
PF0: Extension_Connector (CN14.18), MCU_IO (R205.1 U5.E2)
PF1: Extension_Connector (CN14.20), MCU_IO (R208.1 U5.F3)
PF2: Extension_Connector (CN14.22), MCU_IO (R214.1 U5.F4)
PF3: Extension_Connector (CN14.24), MCU_IO (R218.1 U5.G5)
PF4: Extension_Connector (CN14.26), MCU_IO (R223.1 U5.G6)
PF5: Extension_Connector (CN14.28), MCU_IO (R227.1 U5.G4)
PF6: Extension_Connector (CN9.29), MCU_IO (R153.1 U5.H6)
PF7: Extension_Connector (CN9.31), MCU_IO (R154.1 U5.G2)
PF8: Extension_Connector (CN9.33), MCU_IO (R157.1 U5.F1)
PF9: Extension_Connector (CN9.35), MCU_IO (SB59.1 SB62.1 U5.G3)
PF10: Extension_Connector (CN9.36), MCU_IO (SB55.1 SB58.1 U5.H4)
PF11: Extension_Connector (CN9.38), MCU_IO (SB60.1 U5.M5)
PF12: Extension_Connector (CN15.27), MCU_IO (R225.1 U5.K6)
PF13: Extension_Connector (CN15.25), MCU_IO (R221.1 U5.M6)
PF14: Extension_Connector (CN15.23), MCU_IO (R219.1 U5.L6)
PF15: Extension_Connector (CN15.21), MCU_IO (R215.1 U5.N6)
PG0: Extension_Connector (CN15.19), MCU_IO (R209.1 U5.J6)
PG1: Extension_Connector (CN15.17), MCU_IO (R203.1 U5.H7)
PG2: Extension_Connector (CN15.24), MCU_IO (R217.1 U5.K13)
PG3: Extension_Connector (CN15.26), MCU_IO (R222.1 U5.J8)
PG4: Extension_Connector (CN15.28), MCU_IO (R226.1 U5.H11)
PG5: Extension_Connector (CN15.30), MCU_IO (R229.1 U5.J9)
PG6: Extension_Connector (CN9.11), MCU_IO (SB33.1 SB38.1 U5.H10)
PG7: Extension_Connector (CN9.12), MCU_IO (JP10.2 SB31.1 U5.G8)
PG8: Extension_Connector (CN9.13), MCU_IO (JP11.2 SB11.1 U5.H9)
PG9: Extension_Connector (CN14.13), MCU_IO (SB107.1 SB108.1 U5.A7)
PG10: Extension_Connector (CN14.11), MCU_IO (SB102.1 SB103.1 U5.C7)
PG12: Extension_Connector (CN14.7), MCU_IO (R187.1 U5.E6)
PG15: Extension_Connector (CN9.14), MCU_IO (SB35.1 U5.A5)
PH0: Extension_Connector (CN10.31), MCU_CLOCK_&_RESET (SB89.1)
PH0-OSC_IN: MCU_CLOCK_&_RESET (R25.1 SB89.2 SB90.2), MCU_IO (U5.H1)
PH1: Extension_Connector (CN10.33), MCU_CLOCK_&_RESET (SB88.1)
PH1-OSC_OUT: MCU_CLOCK_&_RESET (R26.1 SB88.2), MCU_IO (U5.J1)
PH2: Extension_Connector (CN9.5), MCU_IO (SB20.2 U5.F10)
PH3: Extension_Connector (CN9.7), MCU_CLOCK_&_RESET (SB22.2)
PH3-BOOT0: MCU_CLOCK_&_RESET (JP3.1 R2.2 SB22.1), MCU_IO (U5.C5)
PH4: Extension_Connector (CN10.13), MCU_IO (R178.2 U5.E10)
PH5: Extension_Connector (CN10.14), MCU_IO (R145.2 U5.F9)
PH6: Extension_Connector (CN10.15), MCU_IO (R179.2 U5.E11)
PH7: Extension_Connector (CN9.41), MCU_IO (U5.F8), PERIPHERAL (R239.1)
PH8: Extension_Connector (CN10.16), MCU_IO (SB96.1 U5.D12), Camera (CN16.31)
PH13: Extension_Connector (CN9.8), MCU_IO (SB21.2 U5.C12)
PH15: Extension_Connector (CN9.9), MCU_IO (SB27.2 U5.A13)
PI0: Extension_Connector (CN10.41), MCU_IO (SB74.2 U5.B12)
PI1: Extension_Connector (CN10.5), MCU_IO (R177.2 U5.A12)
PI2: Extension_Connector (CN10.6), MCU_IO (SB101.1 U5.D11), Camera (CN16.17)
PI3: Extension_Connector (CN10.7), MCU_IO (SB98.1 U5.D10), Camera (CN16.19)
PI5: Extension_Connector (CN10.9), MCU_IO (SB112.1 U5.B3), Camera (CN16.32)
SAI1_FS_B: AUDIO (U25.1), MCU_IO (SB62.2)
SAI1_MCLK_B: AUDIO (U25.30), MCU_IO (R154.2)
SAI1_SCK_B: AUDIO (U25.31), MCU_IO (R157.2)
SAI1_SDIN_B: AUDIO (U25.32), MCU_IO (R153.2)
SAI1_SDOUT_A: AUDIO (U25.29), MCU_IO (R206.1)
SDCARD_DETECT: MCU_IO (SB74.1), SDCARD (CN30.10 R174.1)
SDIO1_CLK: MCU_IO (SB91.2), SDCARD (CN30.5 U44.1 U44.10)
SDIO1_CMD: MCU_IO (R171.1), SDCARD (CN30.3 R169.1 U44.2 U44.9)
SDIO1_D0: MCU_IO (SB84.2), SDCARD (CN30.7 R172.1 U46.2 U46.9)
SDIO1_D1: MCU_IO (SB83.2), SDCARD (CN30.8 R173.1 U46.1 U46.10)
SDIO1_D2: MCU_IO (SB85.2), SDCARD (CN30.1 R165.1 U44.5 U44.6)
SDIO1_D3: MCU_IO (R168.2), SDCARD (CN30.2 R166.1 U44.4 U44.7)
SHIELD: MCU_IO (JP12.1 SB34.1 U5.N13), PERIPHERAL (R22.1)
SHIELD_CS: MCU_IO (JP9.1 SB23.1 U5.M12), PERIPHERAL (C21.1)
SmartCard_3/5V: SMARTCARD (R75.2 U21.3), MFX_IO_expander (U15.31)
SMARTCARD_CLK: MCU_IO (SB42.2), SMARTCARD (U21.24)
SMARTCARD_CMDVCC: SMARTCARD (R86.1 U21.19), MFX_IO_expander (U15.30)
SMARTCARD_IO: MCU_IO (SB116.2), SMARTCARD (U21.26)
SMARTCARD_OFF: SMARTCARD (R88.2 U21.23), MFX_IO_expander (U15.16)
SMARTCARD_RST: SMARTCARD (R87.1 U21.20), MFX_IO_expander (U15.17)
SPI3_MISO: MCU_IO (SB102.2), PMOD_STMOD+ (U1.6)
SPI3_MISO2: MCU_IO (SB37.2), PMOD_STMOD+ (CN7.9)
SPI3_MOSI: MCU_IO (SB94.2), PMOD_STMOD+ (U1.1)
SPI3_MOSI2: MCU_IO (SB36.2), PMOD_STMOD+ (CN7.8)
SPI3_SCK: MCU_IO (SB108.2), PMOD_STMOD+ (U1.14)
SPI_NSS: MCU_IO (SB18.2), PMOD_STMOD+ (U1.9)
STLK_MCO: MCU_CLOCK_&_RESET (SB90.1), ST_LINK_V3E (C108.2 R116.2)
STMOD+_ADC: MCU_IO (SB79.2), PMOD_STMOD+ (CN7.13)
STMOD+_INT: MCU_IO (SB71.2), PMOD_STMOD+ (CN7.11 R135.2)
STMOD+_PWM: MCU_IO (SB82.2), PMOD_STMOD+ (CN7.14)
STMOD+_RST: PMOD_STMOD+ (CN7.12 R134.2), MFX_IO_expander (U15.27)
TAMPER_KEY: MCU_CLOCK_&_RESET (JP35.2), MCU_IO (SB78.2)
TKEY: MCU_IO (SB24.1 SB29.1 U5.H13), PERIPHERAL (R21.1)
TKEY_CS: MCU_IO (SB25.1 SB30.1 U5.G12), PERIPHERAL (C20.1)
TRACE_CLK: JTAG_TRACE (CN12.12 U9.1), MCU_IO (R184.1)
TRACE_D0: JTAG_TRACE (CN12.14 R30.1 U7.5), MCU_IO (SB77.2)
TRACE_D1: JTAG_TRACE (CN12.16 R31.1 U7.4), MCU_IO (SB81.2)
TRACE_D2: JTAG_TRACE (CN12.18 U7.3), MCU_IO (R194.1)
TRACE_D3: JTAG_TRACE (CN12.20 U7.1), MCU_IO (SB92.2)
UART_CTS: FDCAN_RS232 (R161.1), MCU_IO (JP12.2), PMOD_STMOD+ (U1.7)
UART_RTS: FDCAN_RS232 (R167.2 U45.3), MCU_IO (SB38.2), PMOD_STMOD+ (U1.12)
UART_RX: FDCAN_RS232 (U43.17), MCU_IO (JP11.3), PMOD_STMOD+ (U1.4)
UART_TX: FDCAN_RS232 (R170.2 U45.2), MCU_IO (JP10.3), PMOD_STMOD+ (U1.15)
UCPD_CC1: MCU_IO (SB19.2), USB_TYPEC (SB12.1 U2.3 U42.1)
UCPD_CC2: MCU_IO (SB52.1), USB_TYPEC (SB9.2 U2.1 U42.3)
UCPD_DISCHARGE: MCU_IO (SB21.1), USB_TYPEC (Q6.1 R20.2)
UCPD_FRSCC1: MCU_IO (SB33.2), USB_TYPEC (Q11.1 R137.1)
UCPD_FRSCC2: MCU_IO (SB31.2), USB_TYPEC (Q10.1 R136.2)
UCPD_PWR: MCU_IO (SB11.2), USB_TYPEC (SB10.2 U2.12 U42.20)
UCPD_SOURCE_EN: MCU_IO (SB20.1), USB_TYPEC (Q2.1 R13.2)
USB_FS_N: MCU_IO (R139.1 U5.G13), USB_TYPEC (CN1.A7 CN1.B7 U3.1 U3.6)
USB_FS_P: MCU_IO (R140.1 U5.F13), USB_TYPEC (CN1.A6 CN1.B6 U3.3 U3.4)
VBUS_SENSE: MCU_IO (SB75.2), USB_TYPEC (C18.2 R11.1 R12.2)

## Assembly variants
U575AIQ: not fitted C3 C4 C5 C6 C7 C8 C9 C11 C12 C17 C19 C22 C24 C108 C110 C114 C115 C117 C130 C138 CN13 CN19 CN20 CN28 D2 F1 HW5 HW6 HW19 Q2 Q3 Q4 Q5 Q6 R4 R10 R13 R14 R15 R18 R19 R20 R30 R31 R36 R41 R43 R47 R49 R51 R52 R55 R61 R63 R76 R78 R89 R90 R103 R113 R114 R116 R119 R120 R121 R124 R139 R140 R174 R191 R201 R212 R231 R232 R249 SB1 SB9 SB11 SB12 SB13 SB14 SB17 SB23 SB24 SB25 SB29 SB30 SB31 SB33 SB34 SB35 SB43 SB44 SB45 SB47 SB48 SB50 SB51 SB53 SB54 SB57 SB58 SB59 SB61 SB63 SB65 SB66 SB67 SB69 SB73 SB80 SB86 SB87 SB88 SB89 SB90 SB107 SB113 SB117 SB124 SB128 SB129 SB130 SB131 SB132 SB133 SB137 SB138 SB141 SB143 U2 U35 U51
U575AIQ_S: not fitted C3 C4 C5 C6 C7 C8 C9 C11 C12 C17 C19 C22 C24 C108 C110 C114 C115 C117 C130 C138 CN13 CN19 CN20 CN28 D2 F1 HW6 HW19 Q2 Q3 Q4 Q5 Q6 R4 R10 R13 R14 R15 R18 R19 R20 R30 R31 R36 R41 R43 R47 R49 R51 R52 R55 R61 R63 R76 R78 R89 R90 R103 R113 R114 R116 R119 R120 R121 R124 R139 R140 R174 R191 R201 R212 R231 R232 R249 SB1 SB9 SB11 SB12 SB13 SB14 SB17 SB23 SB24 SB25 SB29 SB30 SB31 SB33 SB34 SB35 SB43 SB44 SB45 SB47 SB48 SB50 SB51 SB53 SB54 SB57 SB58 SB59 SB61 SB63 SB65 SB66 SB67 SB69 SB73 SB80 SB86 SB87 SB88 SB89 SB90 SB107 SB113 SB117 SB124 SB128 SB129 SB130 SB131 SB132 SB133 SB137 SB138 SB141 SB143 U2 U35 U51; alternate parts C30 -> MCD-01775, C31 -> MCD-01775, C31 -> MCD-01775, C30 -> MCD-01775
